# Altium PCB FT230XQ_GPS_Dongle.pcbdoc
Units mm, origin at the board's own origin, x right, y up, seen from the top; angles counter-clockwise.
Board outline 36.5 x 14.2 mm, 4 copper layers ([1] Top Layer, [2] Ground Plane, [3] Power Plane, [4] Bottom Layer), stack 1.516 mm thick; 36 components, 23 nets, 114 pads, 31 vias.
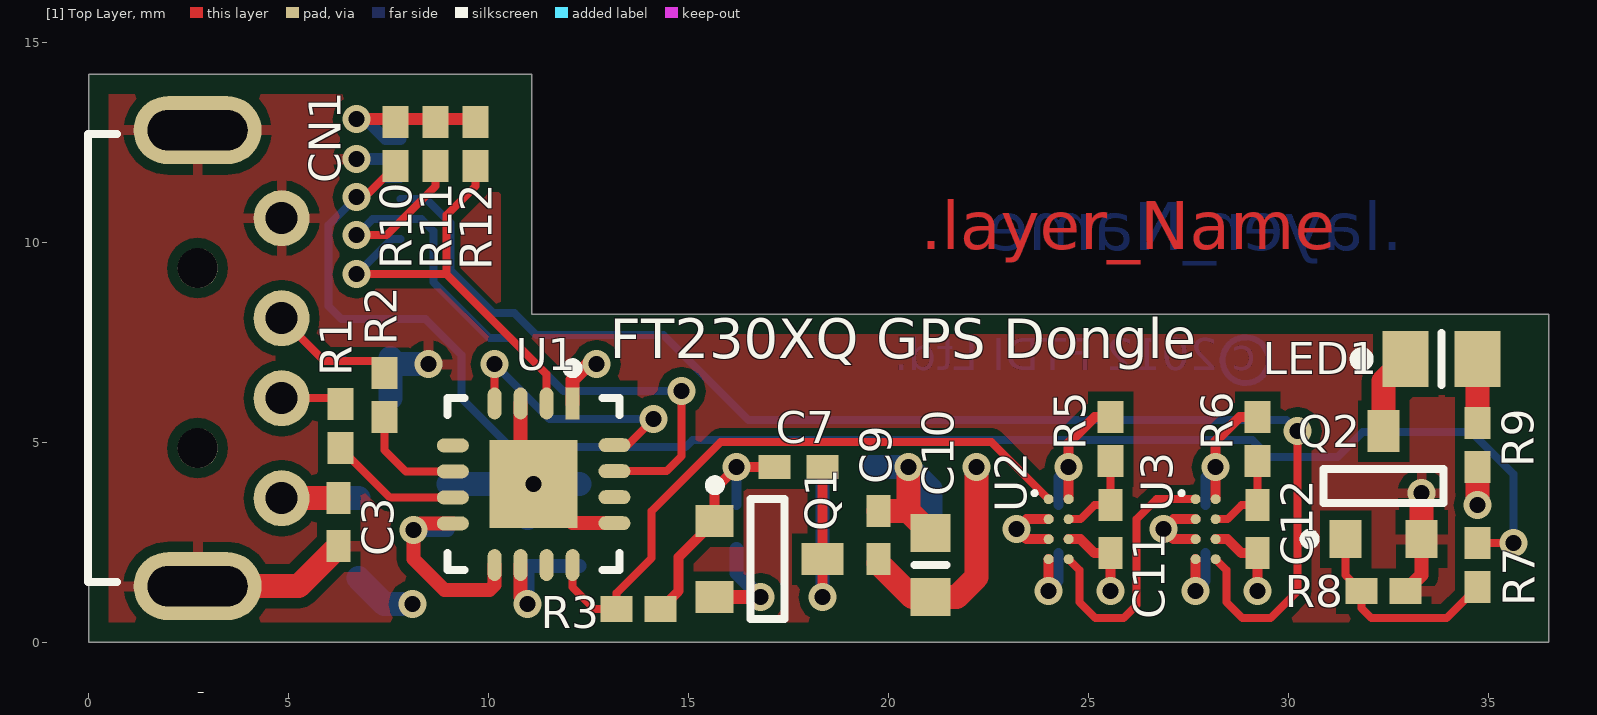
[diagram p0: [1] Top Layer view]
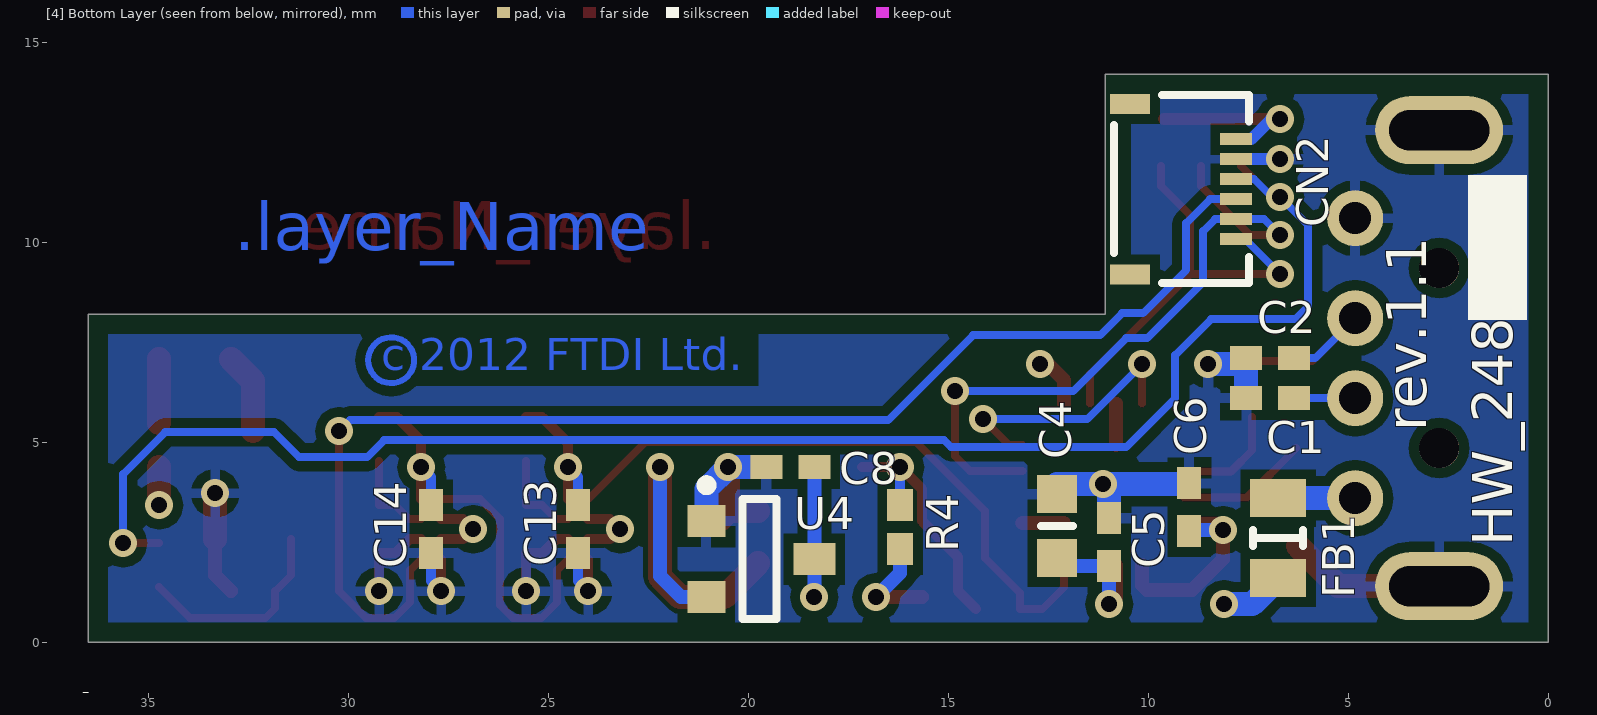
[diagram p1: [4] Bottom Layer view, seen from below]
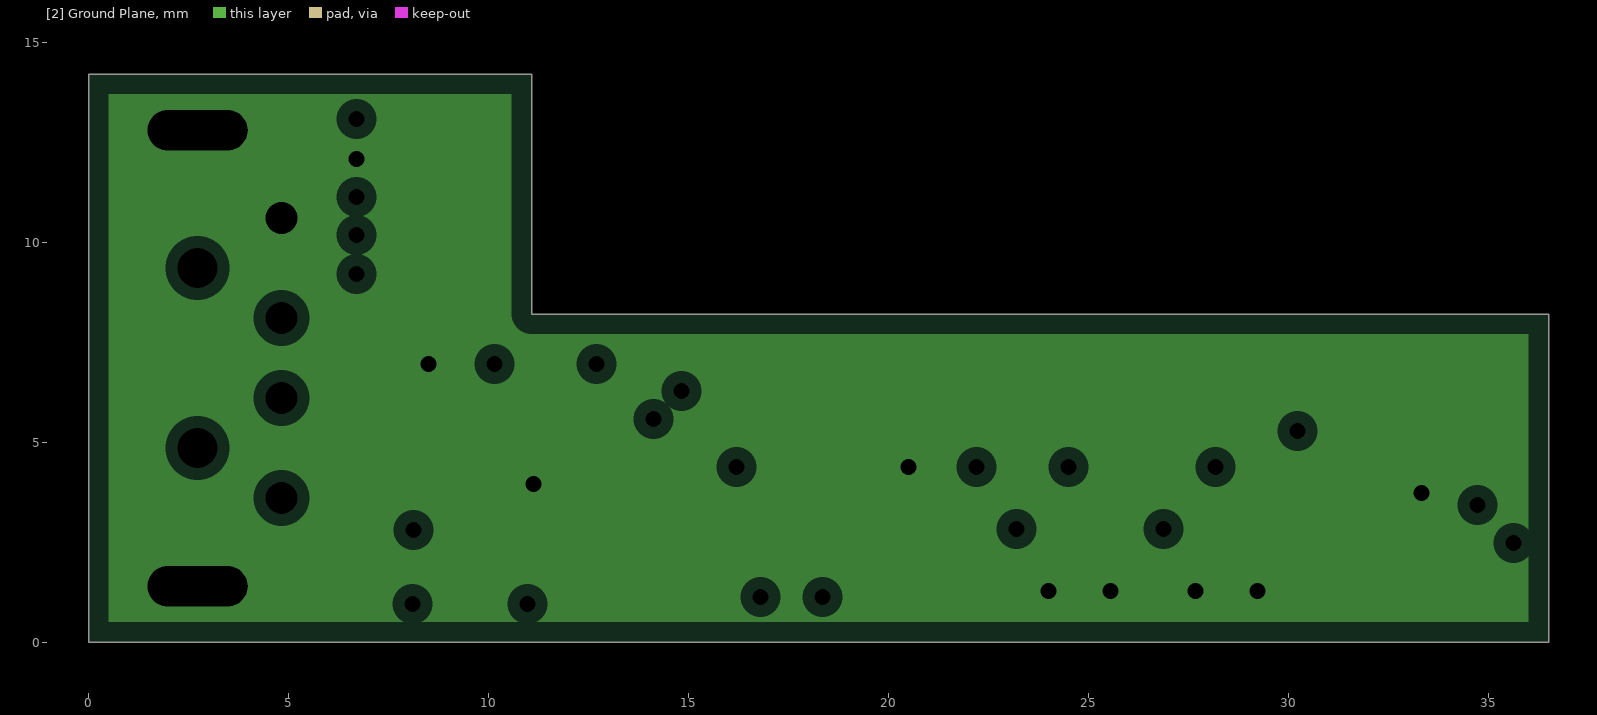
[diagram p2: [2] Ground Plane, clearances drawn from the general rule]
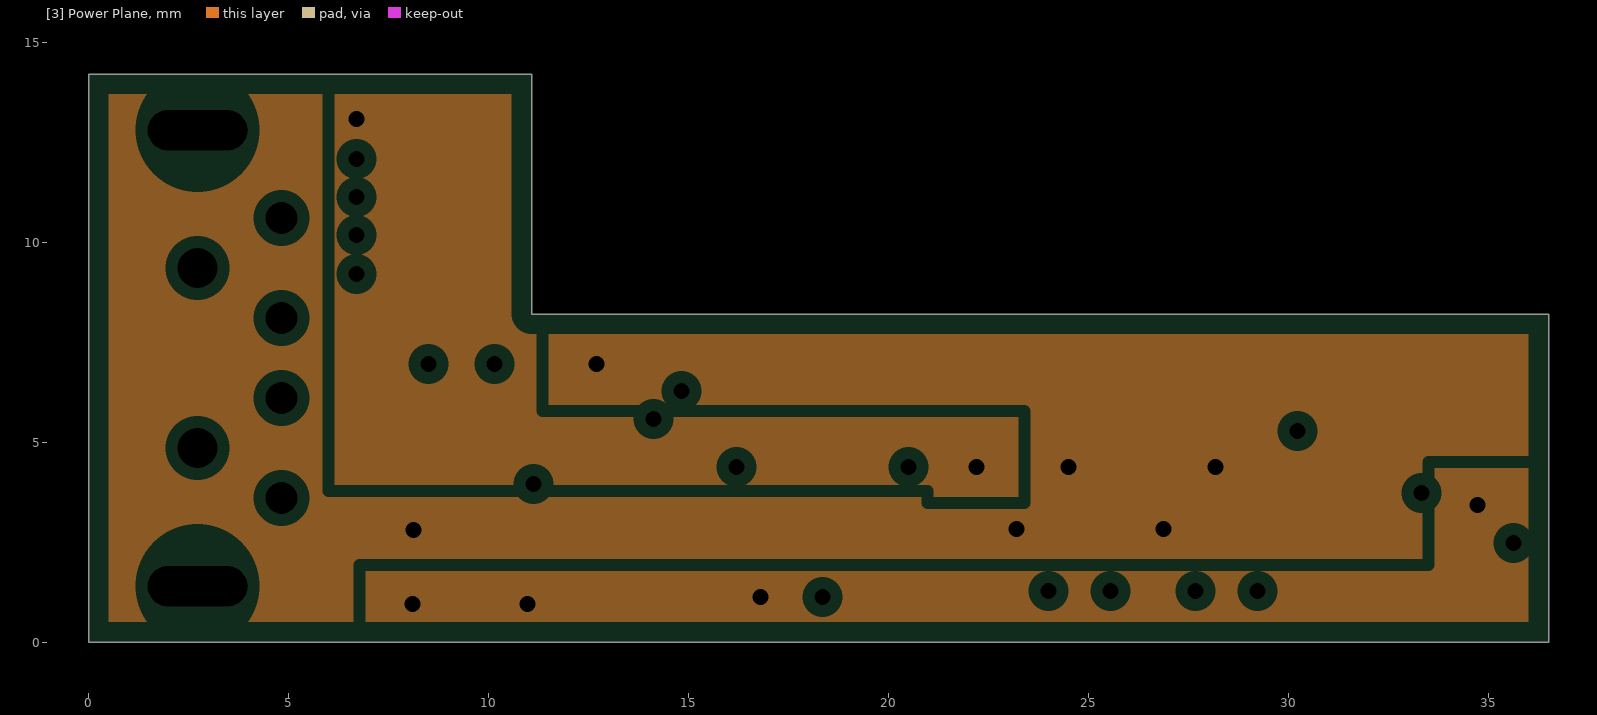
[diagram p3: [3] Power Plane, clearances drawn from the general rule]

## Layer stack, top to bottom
[1] Top Layer: signal copper 0.018
Dielectric: prepreg 0.35, DE104i, Dk 4.8
[2] Ground Plane: plane copper 0.035, net GND
Dielectric: core 0.71, FR-4, Dk 4.8
[3] Power Plane: plane copper 0.035, net 3V3OUT
Dielectric: prepreg 0.35, DE104i, Dk 4.8
[4] Bottom Layer: signal copper 0.018

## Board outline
0,0 0,14.2 11.075,14.2 11.075,8.2 36.5,8.2 36.5,0

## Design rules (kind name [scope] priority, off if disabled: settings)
Clearance Clearance_Polygon [InPoly] p1: gap=0.25
Clearance [All] p2: gap=0.15
ComponentClearance [All] p1: gap=0.1 collisioncheckmode=3 verticalgap=0.1 showdistances=TRUE
DiffPairsRouting [All] p1: maxlimit=0.3 minlimit=0.15 mostfreqgap=0.25 maxuncoupledlength=10
FabricationTestPointUsage TestPointUsage [All] p1: valid=0 allowmultiple=FALSE
FabricationTestpoint Testpoint [All] p1: side=3 testpointundercomponent=TRUE minsize=1.016 maxsize=2.54 preferedsize=1.524 minholesize=0 maxholesize=1.016 preferedholesize=0.813 testpointgrid=0.025 allowsidetop=TRUE allowsidebottom=TRUE usegrid=TRUE gridtolerance=0
HoleSize [All] p1: absolutevalues=TRUE maxlimit=10 minlimit=0.25 maxpercent=80.000 minpercent=20.000
HoleToHoleClearance [All] p1: gap=0.25 allowstackedmicrovias=TRUE
MinimumAnnularRing [All] p1: minimumring=0.1
MinimumSolderMaskSliver [All] p1: minsoldermaskwidth=0.1
NetAntennae [All] p1: netantennaetolerance=0.001
PlaneClearance [All] p1: clearance=0.3
PlaneConnect [All] p1: planeconnectstyle=Relief reliefexpansion=0.3 reliefentries=4 reliefconductorwidth=0.25 reliefairgap=0.25
PolygonConnect [All] p1: connectstyle=Relief reliefconductorwidth=0.25 reliefentries=4 polygonreliefangle="90 Angle" airgapwidth=0.254
RoutingVias [All] p1: holewidth=0.4 width=0.7 viastyle="Through Hole" minholewidth=0.25 minwidth=0.5 maxholewidth=0.6 maxwidth=0.9
SilkToSilkClearance [All] p1: silktosilkclearance=0.15
SilkscreenOverComponentPads [All] p1: minsilkscreentomaskgap=0.15
SolderMaskExpansion [All] p1: expansion=0.1
Width [All] p1: maxlimit=10 minlimit=0.1 preferedwidth=0.25
16 further rules are at their usual default settings.

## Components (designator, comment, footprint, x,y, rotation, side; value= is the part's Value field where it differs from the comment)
C1 "47pF" CAPC1005-0402 6.95,6.1 r0 bottom
C2 "47pF" CAPC1005-0402 6.95,7.1 r0 bottom
C3 "10nF" CAPC1005-0402 6.25,3 r270 top
C4 "4.7uF" CAPC1608-0603 12.275,2.9 r90 bottom
C5 "0.1uF" CAPC1005-0402 10.975,2.5 r90 bottom
C6 "0.1uF" CAPC1005-0402 8.975,3.375 r90 bottom
C7 "0.1uF" CAPC1005-0402 17.75,4.375 r180 top
C8 "0.1uF" CAPC1005-0402 18.947,4.375 r0 bottom
C9 "0.1uF" CAPC1005-0402 19.75,2.675 r90 top
C10 "4.7uF" CAPC1608-0603 21.05,1.925 r90 top
C11 "1uF" CAPC1005-0402 25.55,2.825 r270 top
C12 "0.1uF" CAPC1005-0402 29.225,2.825 r270 top
C13 "0.1uF" CAPC1005-0402 24.25,2.825 r270 bottom
C14 "0.1uF" CAPC1005-0402 27.925,2.825 r270 bottom
CN1 "USB Plug" "CN_USB-PLUG A" 4.825,3.6 r90 top
CN2 "FH34SJ-6S-0.5SH(50)" "CN_6PIN_FPC/FFC; 503480-0600 MOLEX" 9.05,11.325 r90 bottom
FB1 "600R/0.5A" IND_C2012-0805 6.75,2.6 r90 bottom
LED1 "Blue" LEDC2012-0805 33.825,7.075 r0 top
Q1 "IRLML6402" SOT23-3AL 17,2.075 r0 top
Q2 "IRLML2502" SOT23-3AL 32.375,3.925 r90 top
R1 "27R" RESC1005-0402 6.3,5.4 r90 top
R2 "27R" RESC1005-0402 7.4,6.175 r90 top
R3 "2k" RESC1005-0402 13.75,0.825 r0 top
R4 "100k" RESC1005-0402 16.2,2.875 r270 bottom
R5 "1M" RESC1005-0402 25.55,5.075 r90 top
R6 "1M" RESC1005-0402 29.225,5.075 r90 top
R7 "2k" RESC1005-0402 34.725,1.925 r90 top
R8 "100k" RESC1005-0402 32.375,1.275 r180 top
R9 "560R" RESC1005-0402 34.725,4.925 r270 top
R10 "10k" RESC1005-0402 7.675,12.45 r90 top
R11 "10k" RESC1005-0402 8.675,12.45 r90 top
R12 "10k" RESC1005-0402 9.675,12.45 r90 top
U1 "FT230XQ" VQFN65P400X400X90-16N 11.125,3.95 r270 top
U2 "74LVC1G123" BGA6C50P4X2_190X90X50 24.25,2.825 r0 top
U3 "74LVC1G123" BGA6C50P4X2_190X90X50 27.925,2.825 r0 top
U4 "AIC1722A-18" SOT23-3AL 19.697,2.075 r180 bottom

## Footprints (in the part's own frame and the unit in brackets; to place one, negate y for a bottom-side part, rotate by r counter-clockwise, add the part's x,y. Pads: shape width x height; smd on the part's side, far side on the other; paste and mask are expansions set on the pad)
BGA6C50P4X2_190X90X50 [mm] "BGA, 6-Leads, Body 1.9x0.9mm,  Pitch 0.50mm"
  round 0.25 smd: 1(-0.25,0.75) 2(-0.25,0.25) 3(-0.25,-0.25) 4(-0.25,-0.75) 5(0.25,-0.75) 6(0.25,-0.25) 7(0.25,0.25) 8(0.25,0.75)
  silkscreen extent -0.65,0.85 -0.55,0.95, body extent -0.45,-0.95 0.45,0.95, height 0.5
CAPC1005-0402 [mm] "Chip Capacitor, 2-Leads, Body 1.0x0.5mm, IPC Medium Density"
  rect 0.8x0.6 smd: 1(-0.6,0) 2(0.6,0)
  body extent -0.52,-0.28 0.53,0.27, height 0.6
CAPC1608-0603 [mm] "Chip Capacitor; Body 1.6 x 0.8 mm (LxW typ)"
  rect 0.95x1 smd: 1(-0.8,0) 2(0.8,0)
  [1] Top Layer pour cut-out: -0.325,0.75 0.325,0.75 0.325,-0.75 -0.325,-0.75
  silkscreen extent 0,-0.4 0,0.4, body extent -0.8,-0.43 0.8,0.43, height 0.82
"CN_6PIN_FPC/FFC; 503480-0600 MOLEX" [mm] "0.5 mm Pitch, 1.0 mm above the board Top and Bottom Contact, Back-Flip  actuator Flexible Printed Circuit & Flexible Flat Cable ZIF Connectors"
  rect 0.3x0.8 smd: 1(1.25,-1.25) 2(0.75,-1.25) 3(0.25,-1.25) 4(-0.25,-1.25) 5(-0.75,-1.25) 6(-1.25,-1.25)
  rect 0.5x1 smd: 7(2.13,1.4) 8(-2.13,1.4)
  silkscreen extent -2.35,-1.57 2.35,1.8, body extent -2.35,-1.57 2.35,1.85, height 1
"CN_USB-PLUG A" [mm] "Connector; USB2.0, Type A, Thru-Hole; 4 Position; Right Angle"
  round 1 hole 1 unplated: 0(1.25,2.1) 0(5.75,2.1)
  round 1.4 hole 0.8: 1(0,0) 2(2.5,0) 3(4.5,0) 4(7,0)
  oval 1.7x3.2 hole 1 slot 2.5 at 90 deg: 5(9.2,2.1) 6(-2.2,2.1)
  silkscreen extent -2.1,4.12 9.1,4.83, body extent -2.55,1.23 9.45,19.55, height 1.88
IND_C2012-0805 [mm] "Chip Inductor; Body 2 x 1.2 mm (LxW typ)"
  rect 0.95x1.4 smd: 1(-1,0) 2(1,0)
  [1] Top Layer pour cut-out: -0.525,0.9 0.525,0.9 0.525,-0.9 -0.525,-0.9
  silkscreen extent -0.2,-0.63 0.2,0.63, body extent -1,-0.63 1,0.63, height 1
LEDC2012-0805 [mm] "Chip LED diode; Body 2 x 1.3 mm (LxW typ)"
  rect 1.15x1.4 smd: 1(-0.9,0) 2(0.9,0)
  [1] Top Layer pour cut-out: -0.325,0.9 0.325,0.9 0.325,-0.9 -0.325,-0.9
  silkscreen extent -2.15,-0.65 0,0.65, body extent -1,-0.63 1,0.63, height 1
RESC1005-0402 [mm] "Chip Resistor, 2-Leads, Body 1.0x0.5mm, IPC Medium Density"
  rect 0.8x0.65 smd: 1(-0.55,0) 2(0.55,0)
  body extent -0.52,-0.27 0.53,0.28, height 0.4
SOT23-3AL [mm] "SOT23 SMT Package"
  rect 0.95x0.8 smd: 1(-1.35,0.95) 2(-1.35,-0.95)
  rect 1.05x0.8 smd: 3(1.35,0)
  silkscreen extent -1.47,-1.5 0.4,1.97, body extent -1.24,-1.47 1.23,1.45, height 0.95
VQFN65P400X400X90-16N [mm] "VQFN, 16-Leads, Body 4.0x4.0mm (max), Pitch 0.65mm, IPC Medium Density"
  rect 0.8x0.35 smd: 1(-2.02,0.975)
  oval 0.8x0.35 smd: 2(-2.02,0.325) 3(-2.02,-0.325) 4(-2.02,-0.975) 9(2.02,-0.975) 10(2.02,-0.325) 11(2.02,0.325) 12(2.02,0.975)
  oval 0.35x0.8 smd: 5(-0.97,-2.02) 6(-0.32,-2.02) 7(0.33,-2.02) 8(0.98,-2.02) 13(0.975,2.02) 14(0.325,2.02) 15(-0.325,2.02) 16(-0.975,2.02)
  rect 2.2x2.2 smd: 17(0,0)
  silkscreen extent -3.02,-2.15 2.15,2.15, body extent -2,-2 2,2, height 0.9

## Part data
C1 C2 C3 C4 C5 C6 C7 C8 C9 C10 C11 C12 C13 C14: library part CAP_SEMI, "Capacitor bipolar"
CN1: library part CN_USB, "USB connector"
CN2: library part "CN_HEADER 6", "Header, 6-Pin"
FB1: library part FERRITE_BEAD, "Chip Ferrite Bead 0805"
LED1: library part D_LED, "Typical LED diode"
Q1: library part T_MOSFET-P, "P-Channel MOSFET; SOT-23"
Q2: library part T_MOSFET-N, "N-Channel MOSFET"
R1 R2 R3 R4 R5 R6 R7 R8 R9 R10 R11 R12: library part RES1, "Resistor"
U1: library part IC_FT230XQ, "FT230XQ-QFN-16"
U2 U3: library part IC_74LVC1G123, "Retriggerable Monostable Multivibrator"
U4: library part IC_AIC1722A, "300mA Low Dropout Linear Voltage Regulator; Analog Integration Corporation"

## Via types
v1: diameter 0.7, hole 0.4, [1] Top Layer to [4] Bottom Layer, tented both sides, 31 vias

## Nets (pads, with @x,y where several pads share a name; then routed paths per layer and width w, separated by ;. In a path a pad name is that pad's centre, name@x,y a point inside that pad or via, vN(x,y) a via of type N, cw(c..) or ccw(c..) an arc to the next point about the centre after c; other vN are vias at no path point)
1PPS: CN2.3 R7.2 R10.1 | length 40.9
  [1] Top Layer w0.2: v1(6.7,11.125) 6.9,11.125 R10.1 ; R7.2 v1(35.625,2.475)
  [4] Bottom Layer w0.2: CN2.3 7.35,11.575 6.9,11.125 v1(6.7,11.125) 6,10.425 6,8.4 6.325,8.075 8.425,8.075 9.325,7.175 9.325,6.1 10.55,4.875 14.925,4.875 15.1,5.05 29.1,5.05 29.525,4.625 31.225,4.625 31.85,5.25 34.575,5.25 35.625,4.2 v1(35.625,2.475)
3V3OUT: C6.1 C13.1 C14.1 R5.2 R6.2 U1.1 U1.8 U1.9 U2.2 U2.3 U2.8 U3.2 U3.3 U3.8 | length 18.1
  [1] Top Layer w0.25: U2.3 23.45,2.575 v1(23.2,2.825) 23.45,3.075 U2.2 ; U2.8 24.5,4.975 25.15,5.625 R5.2 ; U3.3 27.125,2.575 v1(26.875,2.825) 27.125,3.075 U3.2 ; U3.8 28.175,5.025 28.775,5.625 R6.2
  [1] Top Layer w0.35: U1.8 8.295,2.97 v1(8.125,2.8) 8.125,2.075 8.9,1.3 10.025,1.3 10.15,1.425 U1.9 ; U1.1 12.1,6.55 12.5,6.95 v1(12.7,6.95)
  [4] Bottom Layer w0.25: C13.1 24.25,4.125 v1(24.5,4.375) ; C14.1 27.925,4.125 v1(28.175,4.375)
  [4] Bottom Layer w0.35: v1(8.125,2.8) C6.1@8.975,2.8
GND: C1.2 C2.2 C3.2 C4.2 C5.2 C6.2 C8.2 C9.2 C10.2 C11.2 C12.2 C13.2 C14.2 CN1.4 CN1.5 CN1.6 CN2.2 Q2.2 R8.1 U1.3 U1.13 U1.17 U2.4 U2.6 U3.4 U3.6 U4.1 | length 28.7
  [1] Top Layer w0.25: v1(24,1.275) U2.4 ; U2.6 24.8,2.575 25.15,2.225 C11.2 v1(25.55,1.275) ; v1(27.675,1.275) U3.4 ; U3.6 28.475,2.575 28.825,2.225 C12.2 v1(29.225,1.275)
  [1] Top Layer w0.35: U1.17@10.8,4.925 U1.3 ; U1.17@12.1,2.975 U1.13 ; C10.2@20.75,3.025 C10.2@21.05,3.025 ; R8.1 33.325,1.675 Q2.2
  [1] Top Layer w0.6: CN1.6 5.25,1.4 C3.2 ; C9.2 20.5,3.275 ; v1(20.5,4.375) 20.5,3.275 ; C10.2@20.75,3.025 20.5,3.275 ; Q2.2 v1(33.325,3.725)
  [4] Bottom Layer w0.25: v1(24,1.275) 24.25,1.525 C13.2 ; v1(27.675,1.275) 27.925,1.525 C14.2
  [4] Bottom Layer w0.3: v1(6.7,12.075) CN2.2
  [4] Bottom Layer w0.6: C1.2 C2.2 ; C2.2@7.55,6.95 v1(8.5,6.95) ; C6.2@9,3.95 10.975,3.95 C5.2 ; v1(11.125,3.95) C4.2@12.275,3.95 ; C8.2 v1(20.5,4.375) 21.047,3.828 U4.1
NetC1_1: C1.1 CN1.2 R1.2 | length 3
  [1] Top Layer w0.2: CN1.2 R1.2@6.3,6.1
  [4] Bottom Layer w0.2: CN1.2 C1.1
NetC2_1: C2.1 CN1.3 R2.2 | length 5
  [1] Top Layer w0.2: CN1.3 5.9,7.025 R2.2@7.4,7.025
  [4] Bottom Layer w0.2: CN1.3 5.825,7.1 C2.1
NetC3_1: C3.1 CN1.1 FB1.2 | length 3.3
  [1] Top Layer w0.6: CN1.1 C3.1
  [4] Bottom Layer w0.6: CN1.1 FB1.2
NetC7_1: C7.1 C8.1 Q1.3 U4.3 | length 6.5
  [1] Top Layer w0.25: v1(18.35,1.125) C7.1
  [4] Bottom Layer w0.35: v1@18.347,1.125 C8.1
NetC7_2: C7.2 Q1.1 R3.2 R4.1 | length 6.2
  [1] Top Layer w0.25: R3.2 14.75,1.275 14.75,2.125 Q1.1 15.65,3.825 v1(16.2,4.375) C7.2
  [4] Bottom Layer w0.25: R4.1 v1(16.2,4.375)
NetC9_1: C9.1 C10.1 CN2.1 R10.2 R11.2 R12.2 U4.2 | length 14.2
  [1] Top Layer w0.3: v1(6.7,13.075) R12.2@9.6,13.075
  [1] Top Layer w0.35: C9.1@19.75,1.975 C9.1
  [1] Top Layer w0.6: C9.1@19.75,1.975 20.6,1.125 C10.1 21.7,1.125 22.2,1.625 v1(22.2,4.375)
  [4] Bottom Layer w0.3: v1(6.7,13.075) 6.925,13.075 7.425,12.575 CN2.1
  [4] Bottom Layer w0.35: U4.2 21.675,1.125 22.2,1.65 v1(22.2,4.375)
NetC11_1: C11.1 R5.1 U2.7 | length 2.3
  [1] Top Layer w0.2: U2.7 24.8,3.075 25.15,3.425 C11.1 R5.1
NetC12_1: C12.1 R6.1 U3.7 | length 2.3
  [1] Top Layer w0.2: U3.7 28.475,3.075 28.825,3.425 C12.1 R6.1
NetCN2_4: CN2.4 U3.5 | length 32.9
  [1] Top Layer w0.2: U3.5 28.45,1.8 28.45,1 28.85,0.6 29.55,0.6 30.225,1.275 v1(30.225,5.275)
  [4] Bottom Layer w0.2: CN2.4 8.45,11.075 9.05,10.475 9.05,9.3 10.125,8.225 10.65,8.225 11.2,7.675 14.375,7.675 16.5,5.55 29.95,5.55 v1(30.225,5.275)
NetCN2_5: CN2.5 R11.1 U1.15 | length 17.3
  [1] Top Layer w0.2: v1(6.7,10.175) 7.45,10.175 8.675,11.4 R11.1 ; U1.15 14.45,4.275 14.825,4.65 v1(14.825,6.275)
  [4] Bottom Layer w0.2: v1(6.7,10.175) 7.1,10.575 CN2.5 8.325,10.575 8.625,10.275 8.625,9 10.025,7.6 10.55,7.6 11.875,6.275 v1(14.825,6.275)
NetCN2_6: CN2.6 R12.1 U1.2 | length 11.8
  [1] Top Layer w0.2: 7.475,9.2 v1(6.7,9.2) 8.95,9.2 ; R12.1 9.675,11.4 8.95,10.675 8.95,9.2 ; U1.2 11.45,6.7 8.95,9.2
  [4] Bottom Layer w0.2: v1(6.7,9.2) 7.575,10.075 CN2.6
NetLED1_1: LED1.1 Q2.3 | length 2
  [1] Top Layer w0.6: Q2.3 32.375,6.525 LED1.1
NetLED1_2: LED1.2 R9.1 | length 1.6
  [1] Top Layer w0.6: R9.1 LED1.2
NetQ2_1: Q2.1 R7.1 R8.2 | length 5.2
  [1] Top Layer w0.2: Q2.1 31.425,1.675 R8.2 31.825,0.85 32.075,0.6 33.95,0.6 R7.1
NetR1_1: R1.1 U1.7 | length 3.3
  [1] Top Layer w0.2: R1.1 7.53,3.62 U1.7
NetR2_1: R2.1 U1.6 | length 2.7
  [1] Top Layer w0.2: R2.1 7.4,4.8 7.93,4.27 U1.6
NetR3_1: R3.1 U1.12 U2.1 | length 15.9
  [1] Top Layer w0.2: U1.12 12.1,1.375 12.65,0.825 R3.1 13.2,1.225 14.075,2.1 14.075,3.275 15.8,5 22.575,5 U2.1
NetU1_4: U1.4 U1.16 | length 6.8
  [1] Top Layer w0.2: U1.4 v1(10.15,6.95) ; U1.16 13.475,4.925 v1(14.125,5.575)
  [4] Bottom Layer w0.2: v1(10.15,6.95) 11.525,5.575 v1(14.125,5.575)
NetU2_5: U2.5 U3.1 | length 6.7
  [1] Top Layer w0.2: U2.5 24.775,1.8 24.775,1 25.175,0.6 25.875,0.6 26.2,0.925 26.2,3.075 26.7,3.575 U3.1
VBUS: C4.1 C5.1 FB1.1 Q1.2 R4.2 R9.2 U1.10 | length 8.5
  [1] Top Layer w0.35: U1.10 10.8,1.125 v1(10.975,0.95) ; Q1.2 v1(16.8,1.125)
  [1] Top Layer w0.6: v1(34.725,3.425) R9.2
  [4] Bottom Layer w0.35: v1(10.975,0.95) C5.1 C4.1@12.275,1.9 ; R4.2 16.2,1.725 v1(16.8,1.125)
  [4] Bottom Layer w0.6: FB1.1 7.4,0.95 v1(8.1,0.95)
pads on no net: CN1.0 CN2.7 CN2.8 U1.5 U1.11 U1.14
copper on no net: | length 3.6
  [4] Bottom Layer w0.15: 29.5,7.05 ccw(c28.925,7.05) 29.5,7.05

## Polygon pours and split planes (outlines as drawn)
GND on [1] Top Layer "Top Layer" (solid, pour order 4): 0.5,0.5 0.5,13.7 10.305,13.7 10.305,7.7 35.55,7.7 35.55,0.5 0.5,0.5
GND on [4] Bottom Layer "Top Layer" (solid, pour order 3): 0.5,0.5 0.5,13.7 10.43,13.7 10.43,7.7 36,7.7 36,0.5 0.5,0.5
GND on [2] Ground Plane (split plane): 10.573,8.2 10.582,8.102 10.611,8.008 10.657,7.921 10.72,7.845 10.796,7.782 10.883,7.736 10.977,7.707 11.075,7.698 35.998,7.698 35.998,0.502 0.502,0.502 0.502,13.698 10.573,13.698
NetC9_1 on [3] Power Plane (split plane): 10.573,8.2 10.582,8.102 10.611,8.008 10.657,7.921 10.72,7.845 10.796,7.782 10.883,7.736 10.977,7.707 11.075,7.698 11.199,7.698 11.199,5.775 11.204,5.736 11.219,5.699 11.243,5.668 11.274,5.644 11.311,5.629 11.35,5.624 11.362,5.625 11.375,5.624 23.249,5.624 23.249,3.626 21.126,3.626 21.126,3.775 21.121,3.814 21.106,3.851 21.082,3.882 21.051,3.906 21.014,3.921 20.975,3.926 6.151,3.926 6.151,13.698 10.573,13.698
VBUS on [3] Power Plane (split plane): 35.998,0.502 6.926,0.502 6.926,1.774 33.5,1.774 33.539,1.779 33.576,1.794 33.607,1.818 33.631,1.849 33.646,1.886 33.651,1.925 33.651,4.349 35.998,4.349
3V3OUT on [3] Power Plane (split plane): 5.849,3.775 5.854,3.736 5.869,3.699 5.893,3.668 5.924,3.644 5.961,3.629 6,3.624 20.824,3.624 20.824,3.475 20.829,3.436 20.844,3.399 20.868,3.368 20.899,3.344 20.936,3.329 20.975,3.324 23.4,3.324 23.439,3.329 23.476,3.344 23.507,3.368 23.531,3.399 23.546,3.436 23.551,3.475 23.551,5.775 23.546,5.814 23.531,5.851 23.507,5.882 23.476,5.906 23.439,5.921 23.4,5.926 11.501,5.926 11.501,7.698 35.998,7.698 35.998,4.651 33.5,4.651 33.461,4.646 33.424,4.631 33.393,4.607 33.369,4.576 33.354,4.539 33.349,4.5 33.349,2.076 6.775,2.076 6.736,2.071 6.699,2.056 6.668,2.032 6.644,2.001 6.629,1.964 6.624,1.925 6.624,0.502 0.502,0.502 0.502,13.698 5.849,13.698

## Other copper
[1] Top Layer:
  pour cut-out: 8.525,6.55 13.725,6.55 13.725,1.35 8.525,1.35
  text ".layer_Name" at 20.8,9.825 h1.2
[4] Bottom Layer:
  text ".layer_Name" at 32.85,9.8 h1.2
  text "c 2012 FTDI Ltd." at 29.175,6.8 h0.8
[2] Ground Plane (plane layer: these items are gaps in the copper):
  text ".layer_Name" at 32.6,9.825 h1.2
[3] Power Plane (plane layer: these items are gaps in the copper):
  lines w0.3: 6,14.2 6,3.775 20.975,3.775 20.975,3.475 23.4,3.475 23.4,5.775 11.375,5.775 ; 6.775,-0.025 6.775,1.925 33.5,1.925 33.5,4.5 36.5,4.5 ; 11.35,5.775 11.35,8.2
  text ".layer_Name" at 19.65,9.8 h1.2

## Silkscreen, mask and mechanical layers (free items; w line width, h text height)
Top Overlay:
  text "FT230XQ GPS Dongle" at 13.025,6.775 h1.7
  text ".Printout_Name" at 0.375,-2.5 h1.2
Bottom Overlay:
  rectangle: 0.525,8.05 2,11.675
  text "rev.1.1" at 3.05,5.275 h1 r270
  text "HW_248" at 0.9,2.4 h1 r270
  text ".Printout_Name" at 39,-2.5 h1.2
Mechanical 1:
  lines w0.2: 0,0 36.5,0 36.5,8.2 32.95,8.2 11.075,8.2 11.075,14.2 0,14.2 0,0
  text "Opening for GPS module" at 17.575,12.675 h1
  text ".Plot_File_Name" at 0.375,-4.8 h1.2
Mechanical 15:
  lines w0.1: 12.525,8.55 12.525,14.85 37.525,14.85 37.525,8.55 12.525,8.55
Mechanical 16:
  drawing of 632 lines, arcs and shapes, not listed
  text "1" at -122.75,83.275 h1.8
  text "2" at -53.075,83.225 h1.8
  text "3" at 16.8,83.175 h1.8
  text "4" at 84.34,83.146 h1.8
  text "Revision History" at -150.475,78.95 h2
  text "Changed By" at -91.25,74.425 h2
  text "Change description" at -118.775,74.4 h2
  text "Date" at -150.5,74.375 h2
  text "Revision" at -131.125,74.375 h2
  text "Initial Design" at -118.775,69.7 h1.5
  text "1.0" at -127.975,69.675 h1.5
  text "P. R." at -91.2,69.675 h1.5
  text "10/02/2012" at -150.5,69.65 h1.5
  text "Changes to the layout" at -118.775,66.625 h1.5
  text "1.1" at -127.975,66.6 h1.5
  text "P. R." at -91.2,66.6 h1.5
  text "08/05/2012" at -150.5,66.575 h1.5
  text "A" at 116.575,61.6 h1.8
  text "A" at -155.225,61.475 h1.8
  text "B" at -155.325,14.5 h1.8
  text "B" at 116.675,14.05 h1.8
  text "C" at -155.325,-33.25 h1.8
  text "C" at 116.55,-33.8 h1.8
  text "BUILD STATISTICS" at -150.775,-61.626 h1.52
  text "GENERAL" at -150.978,-65.335 h1.02
  text ".Net_Count" at -141.3,-67.443 h1.02
  text "NETS" at -150.902,-67.494 h0.89
  text ".Component_Count" at -141.3,-69.526 h1.02
  text "COMPONENTS" at -150.876,-69.551 h0.89
  text "Layer Stack Up Detail for:" at -100.1,-69.65 h1.15
  text "TITLE:" at -38.235,-69.854 h1.2
  text "Future Technology Devices International Ltd." at 58.95,-70.325 h1.8
  text ".Pcb_File_Name_No_Path" at -100.025,-72.35 h1.15
  text "PRIMITIVES" at -150.952,-73.031 h1.02
  text "FT230XQ GPS Dongle" at -30.775,-73.38 h6
  text "Unit1, 2 Seaward Place," at 58.95,-73.375 h1.8
  text "Layer" at -100.051,-74.952 h0.9
  text ".Fill_Count" at -141.3,-75.165 h1.02
  text "FILLS" at -150.876,-75.19 h0.89
  text "Centurion Business Park," at 58.9,-76.35 h1.8
  text "Name" at -100.051,-76.752 h0.9
  text ".Track_Count" at -141.3,-77.222 h1.02
  text "TRACKS" at -150.876,-77.273 h0.89
  text "D" at 116.65,-78.798 h1.8
  text "D" at -155.225,-79.05 h1.8
  text "Glasgow, G41 1HH, UK" at 58.9,-79.275 h1.8
  text ".String_Count" at -141.3,-79.305 h1.02
  text "STRINGS" at -150.876,-79.356 h0.89
  text "[1] Top Layer" at -100.051,-80.253 h1.25
  text "*" at -30.775,-80.25 h4
  text ".Arc_Count" at -141.3,-81.413 h1.02
  text "ARC'S" at -150.876,-81.464 h0.89
  text "www.ftdichip.com" at 61.3,-82 h1.8
  text "[2] Ground Plane" at -100.051,-83.934 h1.25
  text "LANDS" at -150.978,-84.486 h1.02
  text "ENGINEER:" at -39,-84.7 h1.2
  text "DATE:" at -0.575,-84.7 h1.2
  text "REV:" at 90.5,-84.7 h1.2
  text "PART No.:" at 58.225,-84.775 h1.2
  text ".Pad_Count" at -141.3,-86.62 h1.02
  text "PADS" at -150.876,-86.671 h0.89
  text "*" at 68.325,-87.605 h1.8
  text "[3] Power Plane" at -100.051,-87.615 h1.25
  text "P. R." at -25.05,-87.705 h1.8
  text "1.0" at 96.6,-87.875 h1.8
  text ".PRINT_DATE" at 1.135,-88.523 h1.8
  text ".Via_Count" at -141.3,-88.703 h1.02
  text "VIA'S" at -150.851,-88.728 h0.89
  text ".Hole_Count" at -141.3,-90.703 h1.02
  text "HOLES (Total)" at -150.851,-90.728 h0.89
  text "[4] Bottom Layer" at -100.051,-91.296 h1.25
  text "PCB DESIGNER:" at -38.95,-92.35 h1.2
  text "FILE NAME:" at -0.7,-92.35 h1.2
  text "DWG No.:" at 58.125,-92.35 h1.2
  text "SCALE:" at 90.475,-92.35 h1.2
  text ".Print_Scale" at 93.475,-95.25 h1.8
  text "P. R." at -25.05,-95.43 h1.8
  text "PRINT SCALE" at -151.054,-95.538 h1.02
  text "HW_248" at 68.325,-95.855 h1.8
  text ".PCB_FILE_NAME_NO_PATH" at 1.135,-96.143 h1.8
  text "A4" at 111,-97.55 h1.8
  text ".Print_Scale" at -141.351,-97.697 h1.02
  text "4" at 84.34,-101.649 h1.8
  text "1" at -125.025,-101.725 h1.8
  text "2" at -54.175,-101.725 h1.8
  text "3" at 14.525,-101.725 h1.8

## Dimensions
0,14.2 to 36.5,8.2 on Mechanical 16
0,0 to 0,14.2 on Mechanical 16
11.075,14.2 to 36.5,8.2 on Mechanical 16
11.075,8.2 to 11.075,14.2 on Mechanical 16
